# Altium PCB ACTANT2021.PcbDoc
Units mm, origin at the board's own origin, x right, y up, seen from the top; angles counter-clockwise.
Board outline 119.38 x 21.59 mm, 2 copper layers (Top Layer, Bottom Layer), stack 1.615 mm thick; 27 components, 12 nets, 72 pads, 288 vias.
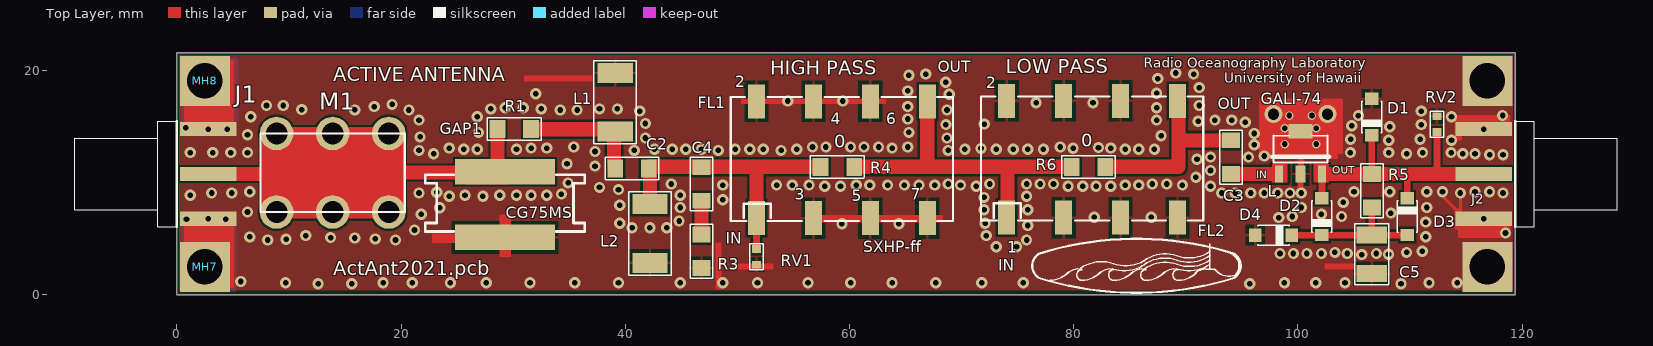
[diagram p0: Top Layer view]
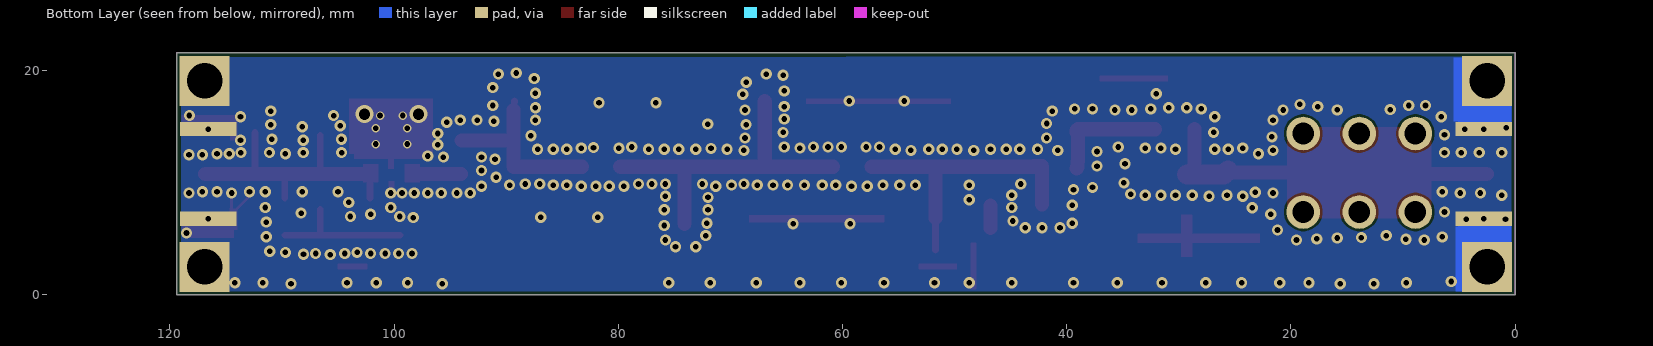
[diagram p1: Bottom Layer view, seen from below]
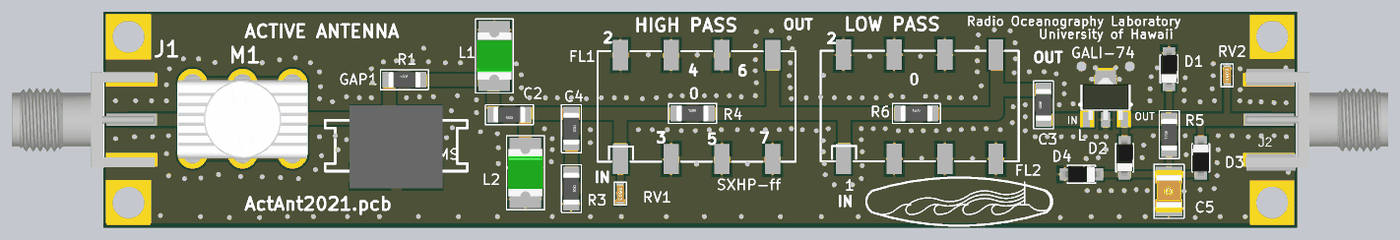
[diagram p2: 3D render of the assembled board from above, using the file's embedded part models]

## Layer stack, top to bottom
Top Solder: solder mask 0.02, Solder Resist, Dk 3.5
Top Layer: signal copper 0.035
Dielectric 1: dielectric 1.545, FR-4, Dk 4.8
Bottom Layer: signal copper 0.035
Bottom Solder: solder mask 0.02, Solder Resist, Dk 3.5

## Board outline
0,0 119.38,0 119.38,21.59 0,21.59

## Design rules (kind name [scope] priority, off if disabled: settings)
Clearance [All] p1: gap=0.2 ignorepadtopadclearanceinfootprint=FALSE
ComponentClearance [All] p1 off: gap=0.254 collisioncheckmode=3 verticalgap=0.254 showdistances=FALSE
Height [All] p1 off: minheight=0 maxheight=25.4 prefheight=12.7
HoleSize [All] p1: absolutevalues=TRUE maxlimit=10 minlimit=0.025 maxpercent=80.000 minpercent=20.000
MinimumSolderMaskSliver [All] p1 off: minsoldermaskwidth=0.254
PlaneClearance PlaneClearance_4 [HasPad('MH7-1')] p1: clearance=1.27
PlaneClearance PlaneClearance_3 [HasPad('MH1-1')] p2: clearance=1.27
PlaneClearance PlaneClearance_2 [HasPad('MH4-1')] p3: clearance=1.27
PlaneClearance PlaneClearance_1 [HasPad('MH8-1')] p4: clearance=1.27
PlaneClearance [All] p5: clearance=0.254
PolygonConnect [All] p1: thpad.connectstyle=Direct thpad.reliefconductorwidth=0.254 thpad.reliefentries=4 thpad.polygonreliefangle="90 Angle" thpad.airgapwidth=0.3 smdpad.connectstyle=Relief smdpad.reliefconductorwidth=0.254 smdpad.reliefentries=4 smdpad.polygonreliefangle="90 Angle" smdpad.airgapwidth=0.3 via.connectstyle=Direct via.reliefconductorwidth=0.254 via.reliefentries=4 via.polygonreliefangle="90 Angle" via.airgapwidth=0.254
RoutingPriority [All] p1: routingpriority=2
RoutingVias [All] p1: holewidth=1 width=3 viastyle="Through Hole" minholewidth=0.2 minwidth=0.5 maxholewidth=0.711 maxwidth=1.27
SilkToSilkClearance [All] p1 off: silktosilkclearance=0.254
SilkToSolderMaskClearance [IsPad] p1 off: minsilkscreentomaskgap=0.254 clearancetoexposedcopper=TRUE
SolderMaskExpansion [All] p1: expansion=0.051 istentingtop=FALSE
Width [All] p1: maxlimit=15 minlimit=0.254 preferedwidth=0.254 minimp=50.000000 maximp=50.000000 favimp=50.000000
22 further rules are at their usual default settings.

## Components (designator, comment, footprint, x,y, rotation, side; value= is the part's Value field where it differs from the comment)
1 "" LOGOTINY 85.6,2.6 r0 top
C2 "820pF" C1206 40.6,11.3 r180 top
C3 "1nF" C1206 94.034,12.295 r90 top
C4 "68pF" C1206 46.8,9.9 r270 top
C5 "4.7uF" C1210 106.585,3.61 r270 top
D1 "BAT-48" SOD123 106.585,15.875 r270 top
D2 "1N4148" SOD123 102.14,6.985 r270 top
D3 "1N4148" SOD123 109.76,6.985 r90 top
D4 "BZT52C8V2-7-F" SOD123 97.822,5.334 r0 top
FL1 "SXHP-ff" FILTX2 59.325,12.065 r0 top
FL2 "" FILTX2 81.64,12.107 r0 top
GAP1 "CG75MS" SG-1 29.275,10.981 r270 top
J1 "" SMA_J610EDGE 0,10.795 r0 top
J2 "1µF" SMA_J610EDGE 119.38,10.795 r180 top
L "GALI-74" GALI-74 100.235,10.795 r0 top
L1 "1.5uH" L1812 39.1,14.57 r90 top
L2 "1.5uH" L1812 42.2,8.1 r270 top
M1 "" 7799 13.9,10.9 r0 top
MH7 "MOUNTHOLE" MOUNTHOLE#1 2.5,2.5 r0 top
MH8 "MOUNTHOLE" MOUNTHOLE#2 2.54,19.05 r0 top
R1 "2.2 ohm" R1206 30.1,14.8 r0 top
R3 "49.9 ohm" R1206 46.8,3.9 r270 top
R4 "ZERO" ZEROHM 57.42,11.43 r0 top
R5 "100K" R1206 106.6,9.3 r90 top
R6 "" ZEROHM 79.82,11.43 r0 top
RV1 "VC06AG183R0YAT1A" R0603 51.7,3.4 r270 top
RV2 "VC06AG183R0YAT1A" R0603 112.395,15.24 r90 top

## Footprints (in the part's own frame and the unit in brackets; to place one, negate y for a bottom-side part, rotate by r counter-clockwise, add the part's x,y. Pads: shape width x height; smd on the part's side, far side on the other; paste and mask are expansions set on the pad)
7799 [mm]
  round 3 hole 1.93 mask+0: 1(-5,-3.5) 2(0,-3.5) 3(5,-3.5) 4(5,3.5) 5(0,3.5) 6(-5,3.5)
  silkscreen extent -6.44,-3.5 6.44,3.5, body extent -6.43,-4.59 6.45,4.47, height 18.97
C1206 [mm]
  rect 1.4x1.6 smd mask+0.05: 1(-1.5,0) 2(1.5,0)
  silkscreen extent -2.4,-1 2.4,1, body extent -1.6,-0.8 1.6,0.8, height 1
C1210 [mm]
  rect 1.524x2.7 smd: 1(-1.724,0) 2(1.705,0)
  silkscreen extent -2.72,-1.5 2.68,1.5, body extent -2.13,-1.35 2.07,1.35, height 0.95
FILTX2 [mil]
  rect 60x120 smd: 1(-300,-205) 2(-300,205) 3(-100,-205) 4(-100,205) 5(100,-205) 6(100,205) 7(300,-205) 8(300,205)
  silkscreen extent -390,-215 390,220
GALI-74 [mil]
  rect 28x60 smd: 1(-75,0) 3(75,0)
  rect 36x60 smd: 2(0,0)
  rect 85x50 smd: 4(0,150)
  Top Layer region: 120,240 -120,240 -120,80 120,80
  Top Layer region: 100,35 45,35 45,-30 100,-30
  Top Layer region: -45,35 -100,35 -100,-30 -45,-30
  Top Layer region: 10,115 -10,115 -10,50 10,50
  silkscreen extent -100,40 100,135, body extent -91,-2 91,165, height 63
L1812 [mm]
  rect 1.78x3.15 smd: 1(0,0) 2(5.23,0)
  silkscreen extent -1.09,-1.87 6.33,1.9, body extent 0.25,-1.74 4.98,1.74, height 1.03
LOGOTINY [mm]
  silkscreen extent -9.29,-2.41 9.29,2.41
MOUNTHOLE#1 [mm]
  rect 4.445x4.445 hole 3.175: 1(0,0)
MOUNTHOLE#2 [mm]
  rect 4.445x4.445 hole 3.175: 1(-0.04,0.05)
R0603 [mm]
  rect 0.7x0.8 smd mask+0.05: 1(-0.7,0) 2(0.7,0)
  silkscreen extent -1.15,-0.6 1.15,0.6, body extent -1,-0.39 1,0.39, height 0.79
R1206 [mm]
  rect 1.4x1.6 smd mask+0.05: 1(-1.5,0) 2(1.5,0)
  silkscreen extent -2.4,-1 2.4,1, body extent -1.6,-0.8 1.6,0.8, height 1
SG-1 [mil]
  rect 90x350 smd: 1(0,0) 2(230,0)
  silkscreen extent 10,-280 210,280, body extent -49,-183 278,183, height 250
SMA_J610EDGE [mm]
  rect 5x1.27 smd: 1(2.8,0)
  rect 5.08x1.27 hole 0.5: 2(2.8,4) 3(2.8,-4)
  silkscreen extent -9.1,-4.7 0,4.7, body extent -9.14,-4.76 5.13,4.76, height 4.36
SOD123 [mm]
  rect 1.1x1.22 smd: A(-1.635,0) K(1.635,0)
  silkscreen extent -1.4,-0.9 1.4,0.9, body extent -1.85,-0.81 1.85,0.79, height 1.27
ZEROHM [mm]
  rect 1.4x1.6 smd mask+0.05: 1(0,0) 2(3,0)
  silkscreen extent -0.9,-1 3.9,1, body extent -0.1,-0.8 3.1,0.8, height 1

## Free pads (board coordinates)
  rect 4.445x4.445 hole 3.175 mask+0: FIX(116.9,2.5) FIX(116.9,19.1)

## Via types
v1: diameter 1, hole 0.5, Top Layer to Bottom Layer, 280 vias
v2: diameter 0.762, hole 0.508, Top Layer to Bottom Layer, 6 vias
v3: diameter 1.6, hole 1, Top Layer to Bottom Layer, 2 vias

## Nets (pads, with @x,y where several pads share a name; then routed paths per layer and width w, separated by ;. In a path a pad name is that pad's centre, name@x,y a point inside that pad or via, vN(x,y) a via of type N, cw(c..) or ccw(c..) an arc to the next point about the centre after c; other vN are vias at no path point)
ANT: GAP1.1 J1.1 M1.1 M1.2 M1.3 M1.4 M1.5 M1.6 R1.1 | length 26.5
  Top Layer w1.27: J1.1@2.54,10.795 4.182,10.795 7.741,10.795 ; 12.578,10.93 GAP1.1@25.804,10.93 ; R1.1 28.6,11.436 GAP1.1@29.275,10.761
  Top Layer w1.778: GAP1.1@25.634,11.1 25.804,10.93 25.973,10.761 28.5,10.761 GAP1.1@29.275,10.761
GND: C5.2 D1.A D4.A FL1.2 FL1.3 FL1.4 FL1.5 FL1.6 FL1.7 FL2.2 FL2.3 FL2.4 FL2.5 FL2.6 FL2.7 GAP1.2 J1.2 J1.3 J2.2 J2.3 L1.2 L2.2 L.2 L.4 MH7.1 MH8.1 pad.FIX R3.2 RV1.2 RV2.2 | length 10.9
  Top Layer w0.254: v1(112.9,9.2) 113.043,9.057 113.043,8.674 114.116,7.601 114.499,7.601 114.501,7.599 ; v1(114.5,9.1) 114.5,7.738 114.57,7.668 114.57,7.303 115.009,6.864 115.374,6.864 115.882,6.356 115.95,6.287 115.95,6.223 116.39,5.784 ; J2.2@114.501,7.303 114.501,6.796 114.502,6.795 J2.2@115.009,6.795 ; J2.2@115.813,6.287 115.813,6.223 115.882,6.154 116.321,5.715 116.522,5.715 116.707,5.531 v1(118.517,5.531)
  other v1: 12.6,1 15.6,1 95.7,1 109.2,1 9.7,1.1 18.4,1.1 21,1.1 24.4,1.1 27.6,1.1 31.5,1.1 35.5,1.1 39.4,1.1 44.9,1.1 48.7,1.1 51.8,1.1 56.3,1.1 60.1,1.1 63.8,1.1 67.7,1.1 71.8,1.1 75.5,1.1 98.8,1.1 101.6,1.1 104.2,1.1 111.7,1.1 114.2,1.1 5.7,1.2 105.7,3.6 108.085,3.634 98.4,3.7 99.6,3.7 100.8,3.7 102.1,3.7 104.4,3.7 107,3.7 103.3,3.8 109.7,3.8 111.1,3.9 73.1,4.3 74.9,4.3 8.1,4.9 19.5,4.9 75.8,4.9 9.744,4.963 17.7,5 15.875,5.08 13.713,5.116 6.508,5.177 111.4,5.2 11.5,5.3 72.2,5.3 21.2,5.8 40.6,6 42.2,6 43.7,6 75.9,6.2 59.325,6.35 64.405,6.35 39.5,6.4 72.1,6.4 111.4,6.5 44.8,6.6 0.86,6.76 4.36,6.76 98.3,6.9 81.84,6.927 86.92,6.927 99.5,7 103.9,7 21.8,7.2 102.1,7.2 108.3,7.3 6.3,7.4 72,7.6 75.9,7.6 23.456,7.79 44.9,7.8 100.3,7.8 111.5,7.8 39.5,8 104.045,8.255 48.7,8.5 72,8.7 24.3,8.8 27.3,8.8 75.8,8.8 1.2,8.9 25.7,8.9 28.8,8.9 30.3,8.9 31.6,8.9 33,8.9 44.9,8.9 34.3,9 3.1,9.1 4.9,9.1 21.6,9.1 93.2,9.1 94.4,9.1 95.8,9.1 97,9.1 98.2,9.1 99.3,9.1 100.3,9.1 118.3,9.1 23.179,9.172 6.5,9.2 105,9.2 108.2,9.2 111.5,9.2 115.8,9.2 117.1,9.2 39.4,9.4 37.7,9.6 57.8,9.7 59.2,9.7 71.3,9.7 79.5,9.7 80.8,9.7 82,9.7 83.3,9.7 92.2,9.7 48.7,9.8 53.5,9.8 54.9,9.8 56.4,9.8 60.6,9.8 61.8,9.8 63.4,9.8 64.9,9.8 66.2,9.8 67.6,9.8 69.9,9.8 84.6,9.8 85.8,9.8 89.7,9.8 44.1,9.9 68.8,9.9 72.5,9.9 75.8,9.9 77,9.9 78.2,9.9 87,9.9 88.3,9.9 34.9,10 90.9,10.5 92.2,11.1 37.3,11.5 34.8,11.7 91,12.1 92.2,12.3 95.6,12.3 97,12.4 117.1,12.5 118.3,12.5 22.9,12.6 109.7,12.6 114.7,12.6 115.8,12.6 1.2,12.7 3.2,12.7 4.8,12.7 6.3,12.7 104.68,12.7 108.1,12.7 111.125,12.7 113.665,12.7 37.3,12.8 21.6,12.9 40.8,12.9 48.3,12.9 53.9,12.9 68.8,12.9 25.6,13 26.8,13 30.3,13 42.6,13 44.2,13 45.4,13 46.8,13 49.8,13 51.1,13 52.3,13 55.3,13 70.3,13 73.1,13 74.6,13 75.9,13 77.3,13 84.6,13 85.8,13 87.2,13 71.734,13.073 24.3,13.1 31.6,13.1 33,13.1 63.8,13.1 79.951,13.094 83.3,13.1 82.214,13.144 35.4,13.2 56.7,13.2 57.9,13.2 60.1,13.2 61.3,13.2 62.6,13.2 65.2,13.2 78.8,13.2 96.1,13.4 108.1,13.8 113.7,13.8 104.7,13.9 110.9,13.9 41.8,14 68.7,14 21.7,14.1 87.8,14.2 6.3,14.3 96.1,14.4 26.9,14.5 65.3,14.5 4.5,14.8 0.8,14.9 108.2,15 104.8,15.1 68.6,15.2 111,15.2 72.025,15.24 41.8,15.3 95.3,15.4 91.1,15.5 21.6,15.6 87.4,15.6 92.6,15.6 94.1,15.6 65.2,15.7 6.6,15.9 26.8,15.9 113.7,15.9 105.4,16 118.263,16.008 41.3,16.4 111,16.4 15.875,16.51 20.7,16.5 34.2,16.5 35.7,16.5 68.7,16.5 11.148,16.534 28,16.6 32.5,16.6 37.7,16.6 39.3,16.6 29.3,16.7 30.9,16.7 87.4,16.7 17.6,16.8 65.2,16.8 8,16.9 9.5,16.9 91.2,16.9 19.2,17 76.645,17.145 81.725,17.145 54.5,17.3 59.4,17.3 68.9,17.9 32.024,17.95 87.4,18 65.2,18.2 91.2,18.5 68.587,18.975 87.5,19.3 65.3,19.6 66.8,19.7 90.7,19.7 89.1,19.8
  other v2: 98.838,13.462 101.632,13.462 98.838,14.859 101.632,14.859 99.219,16.002 101.251,16.002
  other v3: 97.822,16.129 102.648,16.129
N002: C2.2 L1.1 R1.2 | length 10.3
  Top Layer w1.27: R1.2@32.134,14.775 L1.1@39,14.775 ; C2.2 39.035,11.365 39.035,11.87 39,11.905 39,14.445 39.1,14.545 L1.1@39.1,14.7
N003: C2.1 C4.1 FL1.1 L2.1 R4.1 RV1.1 | length 28.2
  Top Layer w0.61: RV1.1@51.705,4.018 51.705,4.7 ; 51.705,4.7 FL1.1 51.705,4.7
  Top Layer w1.27: L2.1 42.2,11.473 42.953,11.473 42.996,11.43 46.8,11.43 51.705,11.43 ; FL1.1 51.705,11.43 ; R4.1 51.705,11.43
N004: FL1.8 FL2.1 R4.2 R6.1 | length 30
  Top Layer w0.61: FL2.1 FL2.1@74.02,7.027
  Top Layer w1.27: R4.2@60.849,11.43 66.945,11.43 ; FL1.8 66.945,11.43 ; FL2.1@74.105,6.35 74.105,7.027 74.105,11.43 ; R6.1 74.105,11.43 ; 66.945,11.43 74.105,11.43
N005: C4.2 R3.1 | length 3.3
  Top Layer w1.27: R3.1@46.8,5.98 46.8,7.98 46.8,6.675
N006: C3.2 FL2.8 R6.2 | length 15.9
  Top Layer w0.61: FL2.8@89.26,17.187 FL2.8
  Top Layer w1.27: R6.2@83.249,11.43 89.345,11.43 89.345,13.786 ; FL2.8@89.345,16.51 89.345,13.786 ; C3.2@93.963,13.786 89.345,13.786
N007: C3.1 L.1 | length 4.3
  Top Layer w1.27: C3.1 L.1
N008: D1.K D2.A D3.K J2.1 L.3 R5.2 RV2.1 | length 26.2
  Top Layer w0.61: D2.A@102.14,8.636 L.3 ; R5.2@106.585,10.795 D1.K@106.585,14.224 ; D3.K@109.76,8.636 109.76,10.795 ; 112.395,10.795 RV2.1@112.395,14.5
  Top Layer w1.27: L.3 106.585,10.795 109.76,10.795 112.395,10.795 116.631,10.795 J2.1@116.84,10.795
N009: C5.1 D2.K D3.A D4.K R5.1 | length 12.7
  Top Layer w0.61: D4.K@99.473,5.334 D2.K@102.14,5.334 ; D2.K@102.013,5.334 C5.1 ; R5.1@106.585,7.62 C5.1 ; D3.A@109.76,5.334 107.22,5.334 C5.1
N010: 
OUT: 

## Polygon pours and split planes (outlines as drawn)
GND on Bottom Layer "GND_L02_P027" (solid, remove dead copper, pour order 27): 0.311,21.277 0.311,14.232 0.33,14.232 0.33,6.091 0.325,0.334 118.874,0.326 118.992,0.444 118.992,6.094 118.993,7.336 118.978,7.351 118.974,9.939 118.977,11.651 118.969,14.228 118.98,14.216 118.98,15.737 118.992,15.748 118.992,21.202
GND on Mechanical 16 "Top Layer-No Net" (hatched 90Degree grid 0.254 track 0.305, remove dead copper, pour order 2): 0,21.59 119.38,21.59 119.38,0 0,0
GND on Top Layer "Top Layer-GND 1" (solid, remove dead copper, pour order 1): -0.127,22 119.253,22 119.253,0.444 -0.127,0.444

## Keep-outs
Keep-Out Layer:
  lines w0.05: 0,0 0,21.6 119.4,21.6 119.4,0 0,0

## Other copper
Top Layer:
  rectangle net ANT: 7.46,6.8 20.34,15
  rectangle net GND: 96.881,12.108 103.575,12.827
  rectangle net GND: 113.989,5.796 114.629,7.728
  rectangle net GND: 113.989,5.796 118.945,7.367
  rectangle net GND: 113.985,13.77 114.629,14.327
  rectangle net GND: 113.985,14.243 118.962,16.067
  rectangle net GND: 100.006,11.259 100.541,12.786
  rectangle net GND: 0.635,14.605 5.08,20.955
  rectangle net GND: 0.635,0.635 5.08,6.985
  rectangle net GND: 114.3,5.08 118.745,6.35
  rectangle net GND: 22.753,4.615 33.675,5.504
  rectangle net GND: 28.8,3.39 29.816,7.2
  rectangle net GND: 30.988,19.05 37.084,19.558
  rectangle net GND: 49.8,2.286 53.229,2.794
  rectangle net GND: 48.07,0.508 48.578,4.699
  rectangle net GND: 56.277,6.477 68.342,7.112
  rectangle net GND: 50.308,17.018 63.262,17.526
  rectangle net GND: 96.552,12.573 104.045,17.526
  rectangle net GND: 102.394,2.286 105.061,2.794
  rectangle net GND: 99.981,9.525 100.489,10.16
Bottom Layer:
  rectangle net GND: 0.32,14.605 5.08,17.149
  rectangle net GND: 0.336,4.693 5.068,6.38
  rectangle net GND: 0.33,6.091 5.077,7.367
  rectangle net GND: 0.318,0.326 5.334,6.091
  rectangle net GND: 0.326,15.491 5.478,21.202

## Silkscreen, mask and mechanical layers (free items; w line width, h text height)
Top Overlay:
  text "Radio Oceanography Laboratory" at 86.252,20.249 h0.89
  text "LOW PASS" at 73.944,19.757 h1.27
  text "HIGH PASS" at 52.954,19.654 h1.27
  text "ACTIVE ANTENNA" at 13.97,19.05 h1.27
  text "University of Hawaii" at 93.452,18.949 h0.89
  text "0" at 80.655,12.842 h2
  text "0" at 58.63,12.742 h2
  text "ActAnt2021.pcb" at 13.954,1.777 h1.27
Top Paste:
  rectangle: 114.3,5.715 119.253,7.366
  rectangle: 114.3,14.224 119.126,15.875
Mechanical 1:
  lines w0.152: 118.11,21.59 120.015,21.59 118.11,21.59
  lines w0.203: -17.907,-10.033 -12.827,-10.033
  lines w0.254: 119.253,21.59 119.507,21.59 ; 119.38,21.463 119.38,21.717 ; 118.745,21.59 120.015,21.59 ; 118.745,21.59 120.015,21.59 ; 118.745,21.59 120.015,21.59 ; 119.38,20.955 119.38,22.225 119.38,20.955
  text "SPM FIXED" at 80.645,29.337 h2.03
  text "8.2Vz" at 85.852,2.413 h1.02 r90
  text "SMA_J610EDGE" at 96.393,-2.667 h1.27
Mechanical 2:
  text "ActAnt17.pcb" at 0.635,29.21 h3.81
Mechanical 4:
  text "E:\__PROJECT\_PIERREFLAMENT\__LERA4P\__FABRICATION\" at 0,27.305 h1.02
  text "BIDDING FILES on SERVER\ActiveAntenna\20170308\" at 51.435,27.305 h1.02
  text "ActAnt17.pcb" at 98.425,27.305 h1.02
  text "E:\__PROJECT\_PIERREFLAMENT\__LERA4P\__FABRICATION\" at 0,25.4 h1.02
  text "BIDDING FILES on SERVER\ActiveAntenna\20170308\" at 51.435,25.4 h1.02
  text "ActAnt17.net" at 98.425,25.4 h1.02
  text "keepout" at 0,22.225 h1.27
  text "1/16\" brass welding rod" at 0,-1.905 h1.27
  text "E:\__PROJECT\_PIERREFLAMENT\__LERA4P\__FABRICATION\" at 0,-3.81 h1.02
  text "BIDDING FILES on SERVER\ActiveAntenna\20170308\" at 51.435,-3.81 h1.02
  text "ActAnt17.drc" at 98.425,-3.81 h1.02
Mechanical 5:
  lines w0.127: 55.313,-132.989 55.313,-124.308 ; 94.421,-117.483 211.723,-117.483 ; 94.421,-110.658 211.723,-110.658 ; 94.421,-99.568 211.723,-99.568 ; 94.421,-95.302 211.723,-95.302 ; 94.421,-91.036 211.723,-91.036 ; 94.421,-86.771 211.723,-86.771 ; 117.796,-103.833 117.796,-82.505 ; 135.294,-124.308 135.294,-103.833 ; 175.492,-103.833 175.492,-82.505 ; 194.514,-103.833 194.514,-82.505 ; 211.723,-82.505 55.313,-82.505 ; 55.313,-124.308 211.723,-124.308 ; 55.313,-124.308 94.421,-124.308 ; 55.313,-124.308 55.313,-82.505 ; 55.313,-82.505 94.421,-82.505 ; 94.421,-124.308 94.421,-82.505 ; 94.421,-124.308 94.421,-82.505 ; 94.421,-124.308 211.723,-124.308 ; 94.421,-124.308 94.421,-103.833 ; 94.421,-103.833 211.723,-103.833 ; 94.421,-103.833 211.723,-103.833 ; 193.656,-124.308 193.656,-110.658 ; 193.656,-124.308 211.723,-124.308 ; 193.656,-124.308 193.656,-110.658 ; 193.656,-117.483 193.656,-110.658 ; 193.656,-117.483 211.723,-117.483 ; 193.656,-117.483 193.656,-110.658 ; 193.656,-110.658 211.723,-110.658 ; 193.656,-110.658 211.723,-110.658 ; 211.723,-124.308 211.723,-110.658 ; 211.723,-124.308 211.723,-103.833 ; 211.723,-117.483 211.723,-110.658
  lines w0.5: -75.39,-132.939 -75.39,77.061 ; -75.267,-132.977 55.333,-132.977 211.733,-132.977 211.733,77.023 -75.267,77.023
  text "Radio / Oceanography / Laboratory" at 61.26,-97.095 h4
  text "Indice" at 98.482,-102.424 h1.76
  text "Modification" at 137.451,-102.424 h1.76
  text "Date" at 181.125,-102.424 h1.76
  text "Dessine par" at 196.679,-102.506 h1.5
  text "Edition" at 95.391,-108.435 h1.76
  text ":" at 115.33,-108.435 h1.76
  text "CARTE ACTANT-2021" at 139.133,-109.077 h1.8
  text "Dessinateur" at 95.391,-114.446 h1.76
  text "Folio" at 194.531,-114.446 h1.8
  text ":" at 115.33,-114.467 h1.76
  text ":" at 203,-114.467 h1.76
  text "1/1" at 205.377,-114.843 h1.76
  text "RONVEL" at 118.398,-114.958 h1.95
  text ":" at 115.33,-121.06 h1.76
  text "Date" at 95.391,-121.111 h1.76
  text "Ind" at 194.531,-121.111 h1.95
  text "19/10/2021" at 117.283,-122.227 h1.8
Mechanical 7:
  text "PLAN DE CABLAGE" at 182.555,-62.88 h4
Mechanical 9:
  text "PLAN DE PERCAGE" at 188.155,-62.78 h4
Drill Drawing:
  circle w0.1: c-34.645,-27.316 r0.905
  lines w0.1: -37.121,-45.737 155.109,-45.737 ; -37.121,-25.37 155.109,-25.37 ; -22.71,-49.811 -22.71,-21.296 ; -6.763,-49.811 -6.763,-21.296 ; 24.387,-49.811 24.387,-21.296 ; 37.576,-49.811 37.576,-21.296 ; 56.955,-49.811 56.955,-21.296 ; 97.336,-49.811 97.336,-21.296 ; 112.805,-49.811 112.805,-21.296 ; 132.51,-49.811 132.51,-21.296 ; -37.121,-49.811 155.109,-49.811 155.109,-21.296 -37.121,-21.296 -37.121,-49.811 ; -35.551,-44.515 -33.74,-44.515 -33.74,-42.705 -35.551,-42.705 -35.551,-44.515 ; -35.551,-40.442 -34.645,-39.989 -33.74,-40.442 -34.193,-39.537 -33.74,-38.631 -34.645,-39.084 -35.551,-38.631 -35.098,-39.537 -35.551,-40.442 ; -35.551,-35.916 -35.098,-35.916 -35.098,-36.368 -34.193,-36.368 -34.193,-35.916 -33.74,-35.916 -33.74,-35.01 -34.193,-35.01 -34.193,-34.558 -35.098,-34.558 -35.098,-35.01 -35.551,-35.01 -35.551,-35.916 ; -35.551,-30.484 -33.74,-30.484 -34.645,-32.295 -35.551,-30.484
  text "Matiere FR4 16/10eme / TECHNO 2 COUCHES / Cuivre 35 microns 2 faces / Vernis selectif vert 2 faces / Serigraphie blanche face top / Finition NiAu" at 156.723,-3.845 h3
  text "Symbol" at -34.677,-24.147 h1.96
  text "Count" at -21.488,-24.147 h1.96
  text "Hole Size" at -5.541,-24.147 h1.96
  text "Plated" at 25.609,-24.147 h1.96
  text "Hole Type" at 38.798,-24.147 h1.96
  text "Drill Layer Pair" at 58.177,-24.147 h1.96
  text "Via/Pad" at 98.558,-24.147 h1.96
  text "Pad Shape" at 114.028,-24.147 h1.96
  text "Template" at 133.732,-24.147 h1.96
  text "284" at -21.488,-28.221 h1.63
  text "0,500mm (19,69mil)" at -5.541,-28.221 h1.63
  text "PTH" at 25.609,-28.221 h1.63
  text "Round" at 38.798,-28.221 h1.63
  text "Top Layer - Bottom Layer" at 58.177,-28.221 h1.63
  text "(Mixed)" at 98.558,-28.221 h1.63
  text "(Mixed)" at 114.028,-28.221 h1.63
  text "(Mixed)" at 133.732,-28.221 h1.63
  text "6" at -21.488,-32.295 h1.63
  text "0,508mm (20,00mil)" at -5.541,-32.295 h1.63
  text "PTH" at 25.609,-32.295 h1.63
  text "Round" at 38.798,-32.295 h1.63
  text "Top Layer - Bottom Layer" at 58.177,-32.295 h1.63
  text "Via" at 98.558,-32.295 h1.63
  text "Rounded" at 114.028,-32.295 h1.63
  text "v76h51m38" at 133.732,-32.295 h1.63
  text "2" at -21.488,-36.368 h1.63
  text "1,000mm (39,37mil)" at -5.541,-36.368 h1.63
  text "PTH" at 25.609,-36.368 h1.63
  text "Round" at 38.798,-36.368 h1.63
  text "Top Layer - Bottom Layer" at 58.177,-36.368 h1.63
  text "Via" at 98.558,-36.368 h1.63
  text "Rounded" at 114.028,-36.368 h1.63
  text "v160h100m80" at 133.732,-36.368 h1.63
  text "6" at -21.488,-40.442 h1.63
  text "1,930mm (75,98mil)" at -5.541,-40.442 h1.63
  text "PTH" at 25.609,-40.442 h1.63
  text "Round" at 38.798,-40.442 h1.63
  text "Top Layer - Bottom Layer" at 58.177,-40.442 h1.63
  text "Pad" at 98.558,-40.442 h1.63
  text "Rounded" at 114.028,-40.442 h1.63
  text "c300h193m300" at 133.732,-40.442 h1.63
  text "4" at -21.488,-44.515 h1.63
  text "3,175mm (125,00mil)" at -5.541,-44.515 h1.63
  text "PTH" at 25.609,-44.515 h1.63
  text "Round" at 38.798,-44.515 h1.63
  text "Top Layer - Bottom Layer" at 58.177,-44.515 h1.63
  text "Pad" at 98.558,-44.515 h1.63
  text "Rectangle" at 114.028,-44.515 h1.63
  text "(Mixed)" at 133.732,-44.515 h1.63
  text "302 Total" at -21.488,-48.589 h1.63

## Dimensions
2.5,2.5 to 2.5,19.1 on Drill Drawing
0,0 to 2.5,2.5 on Drill Drawing
2.5,2.5 to 116.9,2.5 on Drill Drawing
2.5,2.5 to 0,0 on Drill Drawing
0,0 to 119.4,0 on Drill Drawing
0,21.6 to 0,0 on Drill Drawing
